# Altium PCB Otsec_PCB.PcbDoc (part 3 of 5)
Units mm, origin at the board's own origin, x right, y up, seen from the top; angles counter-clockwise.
Board outline 170 x 120 mm, 3 copper layers (Top Layer, Internal Plane 1, Bottom Layer), stack 1.608 mm thick; 1624 components, 0 nets, 5478 pads, 0 vias.
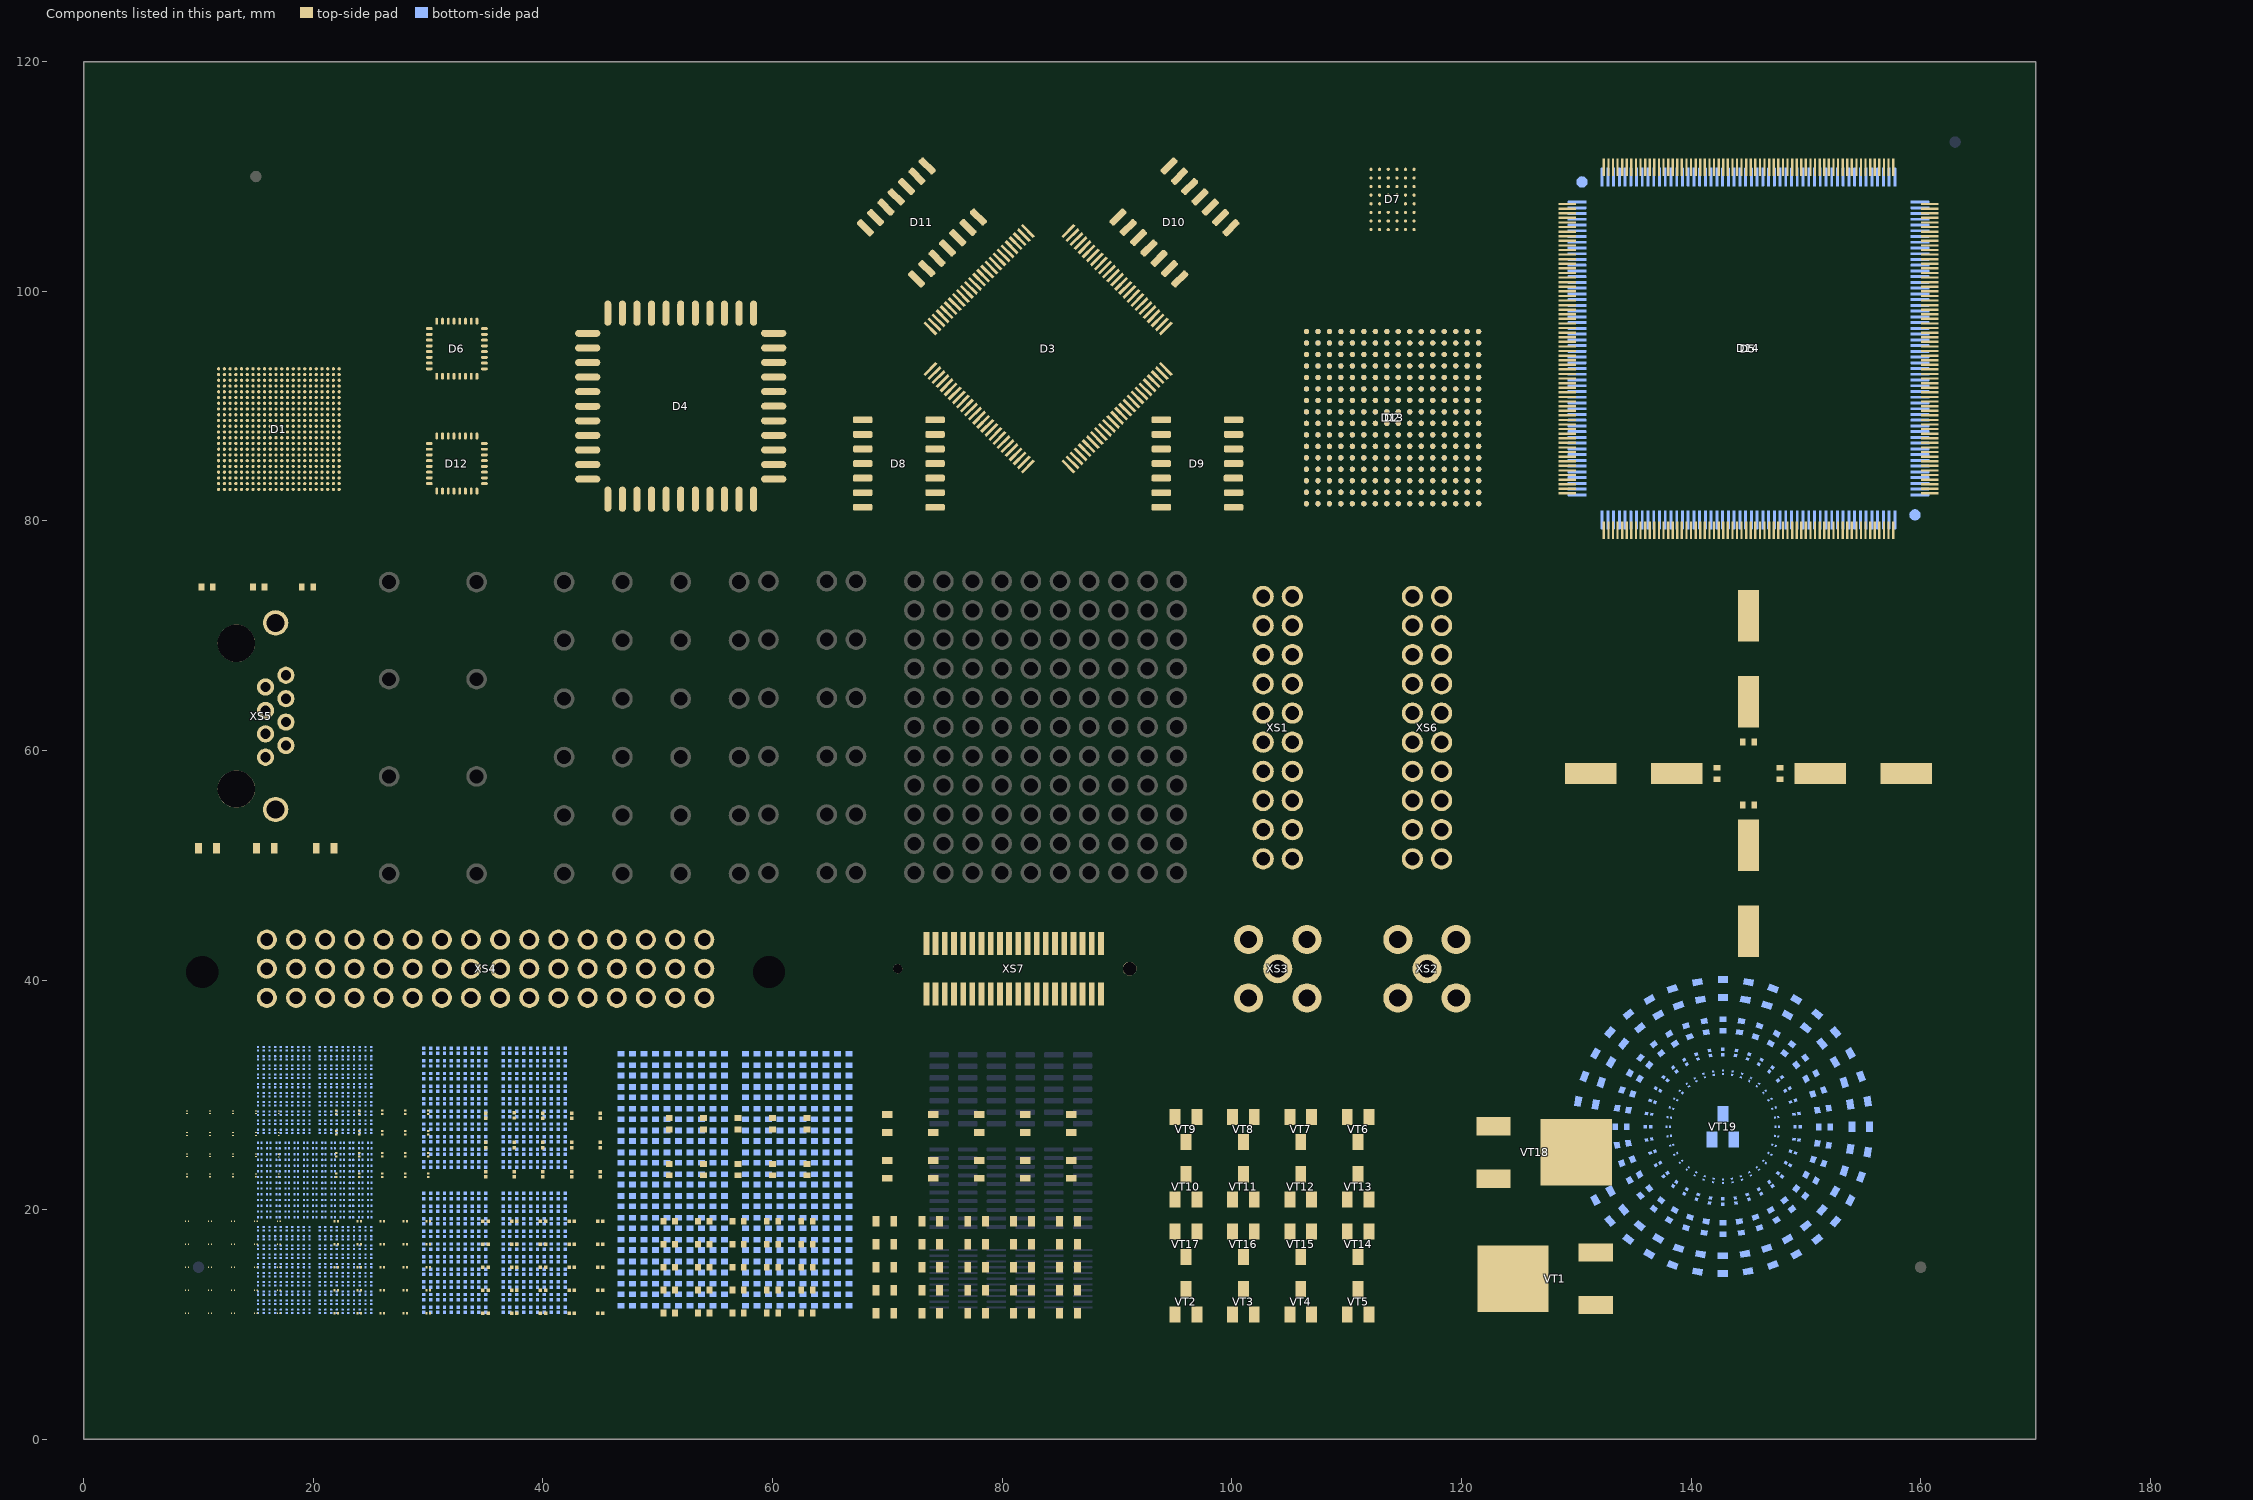
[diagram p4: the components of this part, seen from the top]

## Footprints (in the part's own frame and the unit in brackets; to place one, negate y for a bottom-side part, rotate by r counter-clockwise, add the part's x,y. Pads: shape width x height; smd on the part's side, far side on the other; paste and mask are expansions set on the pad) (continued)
QFN32 [mm]
  rrect100% 0.25x0.6 smd: 1(-1.75,-2.4) 2(-1.25,-2.4) 3(-0.75,-2.4) 4(-0.25,-2.4) 5(0.25,-2.4) 6(0.75,-2.4) 7(1.25,-2.4) 8(1.75,-2.4) 17(1.75,2.4) 18(1.25,2.4) 19(0.75,2.4) 20(0.25,2.4) 21(-0.25,2.4) 22(-0.75,2.4) 23(-1.25,2.4) 24(-1.75,2.4)
  rrect100% 0.6x0.25 smd: 9(2.4,-1.75) 10(2.4,-1.25) 11(2.4,-0.75) 12(2.4,-0.25) 13(2.4,0.25) 14(2.4,0.75) 15(2.4,1.25) 16(2.4,1.75) 25(-2.4,1.75) 26(-2.4,1.25) 27(-2.4,0.75) 28(-2.4,0.25) 29(-2.4,-0.25) 30(-2.4,-0.75) 31(-2.4,-1.25) 32(-2.4,-1.75)
  Top Layer region: -2.7,-1.625 -2.7,-1.875 -2.575,-1.875 -2.575,-1.625
  Top Layer region: -2.7,-1.125 -2.7,-1.375 -2.575,-1.375 -2.575,-1.125
  Top Layer region: -2.7,-0.625 -2.7,-0.875 -2.575,-0.875 -2.575,-0.625
  Top Layer region: -2.7,-0.125 -2.7,-0.375 -2.575,-0.375 -2.575,-0.125
  Top Layer region: -2.7,0.375 -2.7,0.125 -2.575,0.125 -2.575,0.375
  Top Layer region: -2.7,0.875 -2.7,0.625 -2.575,0.625 -2.575,0.875
  Top Layer region: -2.7,1.375 -2.7,1.125 -2.575,1.125 -2.575,1.375
  Top Layer region: -2.7,1.875 -2.7,1.625 -2.575,1.625 -2.575,1.875
  Top Layer region: -1.625,2.7 -1.875,2.7 -1.875,2.575 -1.625,2.575
  Top Layer region: -1.125,2.7 -1.375,2.7 -1.375,2.575 -1.125,2.575
  Top Layer region: -0.625,2.7 -0.875,2.7 -0.875,2.575 -0.625,2.575
  Top Layer region: -0.125,2.7 -0.375,2.7 -0.375,2.575 -0.125,2.575
  Top Layer region: 0.375,2.7 0.125,2.7 0.125,2.575 0.375,2.575
  Top Layer region: 0.875,2.7 0.625,2.7 0.625,2.575 0.875,2.575
  Top Layer region: 1.375,2.7 1.125,2.7 1.125,2.575 1.375,2.575
  Top Layer region: 1.875,2.7 1.625,2.7 1.625,2.575 1.875,2.575
  Top Layer region: 2.7,1.625 2.7,1.875 2.575,1.875 2.575,1.625
  Top Layer region: 2.7,1.125 2.7,1.375 2.575,1.375 2.575,1.125
  Top Layer region: 2.7,0.625 2.7,0.875 2.575,0.875 2.575,0.625
  Top Layer region: 2.7,0.125 2.7,0.375 2.575,0.375 2.575,0.125
  Top Layer region: 2.7,-0.375 2.7,-0.125 2.575,-0.125 2.575,-0.375
  Top Layer region: 2.7,-0.875 2.7,-0.625 2.575,-0.625 2.575,-0.875
  Top Layer region: 2.7,-1.375 2.7,-1.125 2.575,-1.125 2.575,-1.375
  Top Layer region: 2.7,-1.875 2.7,-1.625 2.575,-1.625 2.575,-1.875
  Top Layer region: 1.625,-2.7 1.875,-2.7 1.875,-2.575 1.625,-2.575
  Top Layer region: 1.125,-2.7 1.375,-2.7 1.375,-2.575 1.125,-2.575
  Top Layer region: 0.625,-2.7 0.875,-2.7 0.875,-2.575 0.625,-2.575
  Top Layer region: 0.125,-2.7 0.375,-2.7 0.375,-2.575 0.125,-2.575
  Top Layer region: -0.375,-2.7 -0.125,-2.7 -0.125,-2.575 -0.375,-2.575
  Top Layer region: -0.875,-2.7 -0.625,-2.7 -0.625,-2.575 -0.875,-2.575
  Top Layer region: -1.375,-2.7 -1.125,-2.7 -1.125,-2.575 -1.375,-2.575
  Top Layer region: -1.875,-2.7 -1.625,-2.7 -1.625,-2.575 -1.875,-2.575
  Top Layer region: 0.1,0.1 1.6,0.1 1.6,1.6 0.1,1.6
  Top Layer region: 0.1,-1.6 1.6,-1.6 1.6,-0.1 0.1,-0.1
  Top Layer region: -1.6,-1.6 -0.1,-1.6 -0.1,-0.1 -1.6,-0.1
  Top Layer region: -1.6,0.1 -0.1,0.1 -0.1,1.2 -1.6,1.2
  Top Layer region: -1.025,1.25 -0.1,1.25 -0.1,1.6 -1.025,1.6
  Top Layer region: -1.4,1.6 -1.25,1.6 -1.25,1.25 -1.6,1.25 -1.6,1.4
  Top Layer region: -1.25,1.6 -1.025,1.6 -1.025,1.25 -1.25,1.25
  Top Layer region: -1.6,1.25 -0.1,1.25 -0.1,1.15 -1.6,1.15
  silkscreen extent -3.11,-2.55 2.55,3.17, body extent -2.55,-2.55 2.55,2.55, height 1.04
QFN32_2 [mm]
  rrect100% 0.25x0.6 smd: 1(-1.75,-2.4) 2(-1.25,-2.4) 3(-0.75,-2.4) 4(-0.25,-2.4) 5(0.25,-2.4) 6(0.75,-2.4) 7(1.25,-2.4) 8(1.75,-2.4) 17(1.75,2.4) 18(1.25,2.4) 19(0.75,2.4) 20(0.25,2.4) 21(-0.25,2.4) 22(-0.75,2.4) 23(-1.25,2.4) 24(-1.75,2.4)
  rrect100% 0.6x0.25 smd: 9(2.4,-1.75) 10(2.4,-1.25) 11(2.4,-0.75) 12(2.4,-0.25) 13(2.4,0.25) 14(2.4,0.75) 15(2.4,1.25) 16(2.4,1.75) 25(-2.4,1.75) 26(-2.4,1.25) 27(-2.4,0.75) 28(-2.4,0.25) 29(-2.4,-0.25) 30(-2.4,-0.75) 31(-2.4,-1.25) 32(-2.4,-1.75)
  Top Layer region: -2.7,-1.625 -2.7,-1.875 -2.575,-1.875 -2.575,-1.625
  Top Layer region: -2.7,-1.125 -2.7,-1.375 -2.575,-1.375 -2.575,-1.125
  Top Layer region: -2.7,-0.625 -2.7,-0.875 -2.575,-0.875 -2.575,-0.625
  Top Layer region: -2.7,-0.125 -2.7,-0.375 -2.575,-0.375 -2.575,-0.125
  Top Layer region: -2.7,0.375 -2.7,0.125 -2.575,0.125 -2.575,0.375
  Top Layer region: -2.7,0.875 -2.7,0.625 -2.575,0.625 -2.575,0.875
  Top Layer region: -2.7,1.375 -2.7,1.125 -2.575,1.125 -2.575,1.375
  Top Layer region: -2.7,1.875 -2.7,1.625 -2.575,1.625 -2.575,1.875
  Top Layer region: -1.625,2.7 -1.875,2.7 -1.875,2.575 -1.625,2.575
  Top Layer region: -1.125,2.7 -1.375,2.7 -1.375,2.575 -1.125,2.575
  Top Layer region: -0.625,2.7 -0.875,2.7 -0.875,2.575 -0.625,2.575
  Top Layer region: -0.125,2.7 -0.375,2.7 -0.375,2.575 -0.125,2.575
  Top Layer region: 0.375,2.7 0.125,2.7 0.125,2.575 0.375,2.575
  Top Layer region: 0.875,2.7 0.625,2.7 0.625,2.575 0.875,2.575
  Top Layer region: 1.375,2.7 1.125,2.7 1.125,2.575 1.375,2.575
  Top Layer region: 1.875,2.7 1.625,2.7 1.625,2.575 1.875,2.575
  Top Layer region: 2.7,1.625 2.7,1.875 2.575,1.875 2.575,1.625
  Top Layer region: 2.7,1.125 2.7,1.375 2.575,1.375 2.575,1.125
  Top Layer region: 2.7,0.625 2.7,0.875 2.575,0.875 2.575,0.625
  Top Layer region: 2.7,0.125 2.7,0.375 2.575,0.375 2.575,0.125
  Top Layer region: 2.7,-0.375 2.7,-0.125 2.575,-0.125 2.575,-0.375
  Top Layer region: 2.7,-0.875 2.7,-0.625 2.575,-0.625 2.575,-0.875
  Top Layer region: 2.7,-1.375 2.7,-1.125 2.575,-1.125 2.575,-1.375
  Top Layer region: 2.7,-1.875 2.7,-1.625 2.575,-1.625 2.575,-1.875
  Top Layer region: 1.625,-2.7 1.875,-2.7 1.875,-2.575 1.625,-2.575
  Top Layer region: 1.125,-2.7 1.375,-2.7 1.375,-2.575 1.125,-2.575
  Top Layer region: 0.625,-2.7 0.875,-2.7 0.875,-2.575 0.625,-2.575
  Top Layer region: 0.125,-2.7 0.375,-2.7 0.375,-2.575 0.125,-2.575
  Top Layer region: -0.375,-2.7 -0.125,-2.7 -0.125,-2.575 -0.375,-2.575
  Top Layer region: -0.875,-2.7 -0.625,-2.7 -0.625,-2.575 -0.875,-2.575
  Top Layer region: -1.375,-2.7 -1.125,-2.7 -1.125,-2.575 -1.375,-2.575
  Top Layer region: -1.875,-2.7 -1.625,-2.7 -1.625,-2.575 -1.875,-2.575
  Top Layer region: -0.05,0.025 1.6,0.025 1.6,1.6 -0.05,1.6
  Top Layer region: -0.075,-1.6 1.6,-1.6 1.6,0.05 -0.075,0.05
  Top Layer region: -1.6,-1.6 -0.025,-1.6 -0.025,0.075 -1.6,0.075
  Top Layer region: -1.6,0.025 -0.025,0.025 -0.025,1.15 -1.6,1.15
  Top Layer region: -1.025,1.25 -0.025,1.25 -0.025,1.6 -1.025,1.6
  Top Layer region: -1.4,1.6 -1.25,1.6 -1.25,1.25 -1.6,1.25 -1.6,1.4
  Top Layer region: -1.25,1.6 -1.025,1.6 -1.025,1.25 -1.25,1.25
  Top Layer region: -1.6,1.25 -0.025,1.25 -0.025,1.15 -1.6,1.15
  silkscreen extent -3.11,-2.55 2.55,3.17, body extent -2.55,-2.55 2.55,2.55, height 1.04
QFP100_0.5 [mm]
  rect 1.5x0.254 smd: 1(-8.5,6) 2(-8.5,5.5) 3(-8.5,5) 4(-8.5,4.5) 5(-8.5,4) 6(-8.5,3.5) 7(-8.5,3) 8(-8.5,2.5) 9(-8.5,2) 10(-8.5,1.5) 11(-8.5,1) 12(-8.5,0.5) 13(-8.5,0) 14(-8.5,-0.5) 15(-8.5,-1) 16(-8.5,-1.5) 17(-8.5,-2) 18(-8.5,-2.5) 19(-8.5,-3) 20(-8.5,-3.5) 21(-8.5,-4) 22(-8.5,-4.5) 23(-8.5,-5) 24(-8.5,-5.5) 25(-8.5,-6) 51(8.5,-6) 52(8.5,-5.5) 53(8.5,-5) 54(8.5,-4.5) 55(8.5,-4) 56(8.5,-3.5) 57(8.5,-3) 58(8.5,-2.5) 59(8.5,-2) 60(8.5,-1.5) 61(8.5,-1) 62(8.5,-0.5) 63(8.5,0) 64(8.5,0.5) 65(8.5,1) 66(8.5,1.5) 67(8.5,2) 68(8.5,2.5) 69(8.5,3) 70(8.5,3.5) 71(8.5,4) 72(8.5,4.5) 73(8.5,5) 74(8.5,5.5) 75(8.5,6)
  rect 0.254x1.5 smd: 26(-6,-8.5) 27(-5.5,-8.5) 28(-5,-8.5) 29(-4.5,-8.5) 30(-4,-8.5) 31(-3.5,-8.5) 32(-3,-8.5) 33(-2.5,-8.5) 34(-2,-8.5) 35(-1.5,-8.5) 36(-1,-8.5) 37(-0.5,-8.5) 38(0,-8.5) 39(0.5,-8.5) 40(1,-8.5) 41(1.5,-8.5) 42(2,-8.5) 43(2.5,-8.5) 44(3,-8.5) 45(3.5,-8.5) 46(4,-8.5) 47(4.5,-8.5) 48(5,-8.5) 49(5.5,-8.5) 50(6,-8.5) 76(6,8.5) 77(5.5,8.5) 78(5,8.5) 79(4.5,8.5) 80(4,8.5) 81(3.5,8.5) 82(3,8.5) 83(2.5,8.5) 84(2,8.5) 85(1.5,8.5) 86(1,8.5) 87(0.5,8.5) 88(0,8.5) 89(-0.5,8.5) 90(-1,8.5) 91(-1.5,8.5) 92(-2,8.5) 93(-2.5,8.5) 94(-3,8.5) 95(-3.5,8.5) 96(-4,8.5) 97(-4.5,8.5) 98(-5,8.5) 99(-5.5,8.5) 100(-6,8.5)
  silkscreen extent -7.9,-7.21 7.21,7.9, body extent -8,-8 8,8, height 1.6
QFP208 [mm]
  rrect40% 0.254x1.65 smd: 1(-12.75,-14.925) 2(-12.25,-14.925) 3(-11.75,-14.925) 4(-11.25,-14.925) 5(-10.75,-14.925) 6(-10.25,-14.925) 7(-9.75,-14.925) 8(-9.25,-14.925) 9(-8.75,-14.925) 10(-8.25,-14.925) 11(-7.75,-14.925) 12(-7.25,-14.925) 13(-6.75,-14.925) 14(-6.25,-14.925) 15(-5.75,-14.925) 16(-5.25,-14.925) 17(-4.75,-14.925) 18(-4.25,-14.925) 19(-3.75,-14.925) 20(-3.25,-14.925) 21(-2.75,-14.925) 22(-2.25,-14.925) 23(-1.75,-14.925) 24(-1.25,-14.925) 25(-0.75,-14.925) 26(-0.25,-14.925) 27(0.25,-14.925) 28(0.75,-14.925) 29(1.25,-14.925) 30(1.75,-14.925) 31(2.25,-14.925) 32(2.75,-14.925) 33(3.25,-14.925) 34(3.75,-14.925) 35(4.25,-14.925) 36(4.75,-14.925) 37(5.25,-14.925) 38(5.75,-14.925) 39(6.25,-14.925) 40(6.75,-14.925) 41(7.25,-14.925) 42(7.75,-14.925) 43(8.25,-14.925) 44(8.75,-14.925) 45(9.25,-14.925) 46(9.75,-14.925) 47(10.25,-14.925) 48(10.75,-14.925) 49(11.25,-14.925) 50(11.75,-14.925) 51(12.25,-14.925) 52(12.75,-14.925) 105(12.75,14.925) 106(12.25,14.925) 107(11.75,14.925) 108(11.25,14.925) 109(10.75,14.925) 110(10.25,14.925) 111(9.75,14.925) 112(9.25,14.925) 113(8.75,14.925) 114(8.25,14.925) 115(7.75,14.925) 116(7.25,14.925) 117(6.75,14.925) 118(6.25,14.925) 119(5.75,14.925) 120(5.25,14.925) 121(4.75,14.925) 122(4.25,14.925) 123(3.75,14.925) 124(3.25,14.925) 125(2.75,14.925) 126(2.25,14.925) 127(1.75,14.925) 128(1.25,14.925) 129(0.75,14.925) 130(0.25,14.925) 131(-0.25,14.925) 132(-0.75,14.925) 133(-1.25,14.925) 134(-1.75,14.925) 135(-2.25,14.925) 136(-2.75,14.925) 137(-3.25,14.925) 138(-3.75,14.925) 139(-4.25,14.925) 140(-4.75,14.925) 141(-5.25,14.925) 142(-5.75,14.925) 143(-6.25,14.925) 144(-6.75,14.925) 145(-7.25,14.925) 146(-7.75,14.925) 147(-8.25,14.925) 148(-8.75,14.925) 149(-9.25,14.925) 150(-9.75,14.925) 151(-10.25,14.925) 152(-10.75,14.925) 153(-11.25,14.925) 154(-11.75,14.925) 155(-12.25,14.925) 156(-12.75,14.925)
  rrect40% 1.65x0.254 smd: 53(14.925,-12.75) 54(14.925,-12.25) 55(14.925,-11.75) 56(14.925,-11.25) 57(14.925,-10.75) 58(14.925,-10.25) 59(14.925,-9.75) 60(14.925,-9.25) 61(14.925,-8.75) 62(14.925,-8.25) 63(14.925,-7.75) 64(14.925,-7.25) 65(14.925,-6.75) 66(14.925,-6.25) 67(14.925,-5.75) 68(14.925,-5.25) 69(14.925,-4.75) 70(14.925,-4.25) 71(14.925,-3.75) 72(14.925,-3.25) 73(14.925,-2.75) 74(14.925,-2.25) 75(14.925,-1.75) 76(14.925,-1.25) 77(14.925,-0.75) 78(14.925,-0.25) 79(14.925,0.25) 80(14.925,0.75) 81(14.925,1.25) 82(14.925,1.75) 83(14.925,2.25) 84(14.925,2.75) 85(14.925,3.25) 86(14.925,3.75) 87(14.925,4.25) 88(14.925,4.75) 89(14.925,5.25) 90(14.925,5.75) 91(14.925,6.25) 92(14.925,6.75) 93(14.925,7.25) 94(14.925,7.75) 95(14.925,8.25) 96(14.925,8.75) 97(14.925,9.25) 98(14.925,9.75) 99(14.925,10.25) 100(14.925,10.75) 101(14.925,11.25) 102(14.925,11.75) 103(14.925,12.25) 104(14.925,12.75) 157(-14.925,12.75) 158(-14.925,12.25) 159(-14.925,11.75) 160(-14.925,11.25) 161(-14.925,10.75) 162(-14.925,10.25) 163(-14.925,9.75) 164(-14.925,9.25) 165(-14.925,8.75) 166(-14.925,8.25) 167(-14.925,7.75) 168(-14.925,7.25) 169(-14.925,6.75) 170(-14.925,6.25) 171(-14.925,5.75) 172(-14.925,5.25) 173(-14.925,4.75) 174(-14.925,4.25) 175(-14.925,3.75) 176(-14.925,3.25) 177(-14.925,2.75) 178(-14.925,2.25) 179(-14.925,1.75) 180(-14.925,1.25) 181(-14.925,0.75) 182(-14.925,0.25) 183(-14.925,-0.25) 184(-14.925,-0.75) 185(-14.925,-1.25) 186(-14.925,-1.75) 187(-14.925,-2.25) 188(-14.925,-2.75) 189(-14.925,-3.25) 190(-14.925,-3.75) 191(-14.925,-4.25) 192(-14.925,-4.75) 193(-14.925,-5.25) 194(-14.925,-5.75) 195(-14.925,-6.25) 196(-14.925,-6.75) 197(-14.925,-7.25) 198(-14.925,-7.75) 199(-14.925,-8.25) 200(-14.925,-8.75) 201(-14.925,-9.25) 202(-14.925,-9.75) 203(-14.925,-10.25) 204(-14.925,-10.75) 205(-14.925,-11.25) 206(-14.925,-11.75) 207(-14.925,-12.25) 208(-14.925,-12.75)
  round 1 smd mask+0.5: ""(-14.5,-14.5) ""(14.5,14.5)
  silkscreen extent -15.83,-13.52 13.52,15.8, body extent -15.3,-15.3 15.3,15.3, height 4.15
QFP256 [mm]
  rect 1.52x0.2 smd: 1(-15.8,12.6) 2(-15.8,12.2) 3(-15.8,11.8) 4(-15.8,11.4) 5(-15.8,11) 6(-15.8,10.6) 7(-15.8,10.2) 8(-15.8,9.8) 9(-15.8,9.4) 10(-15.8,9) 11(-15.8,8.6) 12(-15.8,8.2) 13(-15.8,7.8) 14(-15.8,7.4) 15(-15.8,7) 16(-15.8,6.6) 17(-15.8,6.2) 18(-15.8,5.8) 19(-15.8,5.4) 20(-15.8,5) 21(-15.8,4.6) 22(-15.8,4.2) 23(-15.8,3.8) 24(-15.8,3.4) 25(-15.8,3) 26(-15.8,2.6) 27(-15.8,2.2) 28(-15.8,1.8) 29(-15.8,1.4) 30(-15.8,1) 31(-15.8,0.6) 32(-15.8,0.2) 33(-15.8,-0.2) 34(-15.8,-0.6) 35(-15.8,-1) 36(-15.8,-1.4) 37(-15.8,-1.8) 38(-15.8,-2.2) 39(-15.8,-2.6) 40(-15.8,-3) 41(-15.8,-3.4) 42(-15.8,-3.8) 43(-15.8,-4.2) 44(-15.8,-4.6) 45(-15.8,-5) 46(-15.8,-5.4) 47(-15.8,-5.8) 48(-15.8,-6.2) 49(-15.8,-6.6) 50(-15.8,-7) 51(-15.8,-7.4) 52(-15.8,-7.8) 53(-15.8,-8.2) 54(-15.8,-8.6) 55(-15.8,-9) 56(-15.8,-9.4) 57(-15.8,-9.8) 58(-15.8,-10.2) 59(-15.8,-10.6) 60(-15.8,-11) 61(-15.8,-11.4) 62(-15.8,-11.8) 63(-15.8,-12.2) 64(-15.8,-12.6) 129(15.8,-12.6) 130(15.8,-12.2) 131(15.8,-11.8) 132(15.8,-11.4) 133(15.8,-11) 134(15.8,-10.6) 135(15.8,-10.2) 136(15.8,-9.8) 137(15.8,-9.4) 138(15.8,-9) 139(15.8,-8.6) 140(15.8,-8.2) 141(15.8,-7.8) 142(15.8,-7.4) 143(15.8,-7) 144(15.8,-6.6) 145(15.8,-6.2) 146(15.8,-5.8) 147(15.8,-5.4) 148(15.8,-5) 149(15.8,-4.6) 150(15.8,-4.2) 151(15.8,-3.8) 152(15.8,-3.4) 153(15.8,-3) 154(15.8,-2.6) 155(15.8,-2.2) 156(15.8,-1.8) 157(15.8,-1.4) 158(15.8,-1) 159(15.8,-0.6) 160(15.8,-0.2) 161(15.8,0.2) 162(15.8,0.6) 163(15.8,1) 164(15.8,1.4) 165(15.8,1.8) 166(15.8,2.2) 167(15.8,2.6) 168(15.8,3) 169(15.8,3.4) 170(15.8,3.8) 171(15.8,4.2) 172(15.8,4.6) 173(15.8,5) 174(15.8,5.4) 175(15.8,5.8) 176(15.8,6.2) 177(15.8,6.6) 178(15.8,7) 179(15.8,7.4) 180(15.8,7.8) 181(15.8,8.2) 182(15.8,8.6) 183(15.8,9) 184(15.8,9.4) 185(15.8,9.8) 186(15.8,10.2) 187(15.8,10.6) 188(15.8,11) 189(15.8,11.4) 190(15.8,11.8) 191(15.8,12.2) 192(15.8,12.6)
  rect 0.2x1.52 smd: 65(-12.6,-15.8) 66(-12.2,-15.8) 67(-11.8,-15.8) 68(-11.4,-15.8) 69(-11,-15.8) 70(-10.6,-15.8) 71(-10.2,-15.8) 72(-9.8,-15.8) 73(-9.4,-15.8) 74(-9,-15.8) 75(-8.6,-15.8) 76(-8.2,-15.8) 77(-7.8,-15.8) 78(-7.4,-15.8) 79(-7,-15.8) 80(-6.6,-15.8) 81(-6.2,-15.8) 82(-5.8,-15.8) 83(-5.4,-15.8) 84(-5,-15.8) 85(-4.6,-15.8) 86(-4.2,-15.8) 87(-3.8,-15.8) 88(-3.4,-15.8) 89(-3,-15.8) 90(-2.6,-15.8) 91(-2.2,-15.8) 92(-1.8,-15.8) 93(-1.4,-15.8) 94(-1,-15.8) 95(-0.6,-15.8) 96(-0.2,-15.8) 97(0.2,-15.8) 98(0.6,-15.8) 99(1,-15.8) 100(1.4,-15.8) 101(1.8,-15.8) 102(2.2,-15.8) 103(2.6,-15.8) 104(3,-15.8) 105(3.4,-15.8) 106(3.8,-15.8) 107(4.2,-15.8) 108(4.6,-15.8) 109(5,-15.8) 110(5.4,-15.8) 111(5.8,-15.8) 112(6.2,-15.8) 113(6.6,-15.8) 114(7,-15.8) 115(7.4,-15.8) 116(7.8,-15.8) 117(8.2,-15.8) 118(8.6,-15.8) 119(9,-15.8) 120(9.4,-15.8) 121(9.8,-15.8) 122(10.2,-15.8) 123(10.6,-15.8) 124(11,-15.8) 125(11.4,-15.8) 126(11.8,-15.8) 127(12.2,-15.8) 128(12.6,-15.8) 193(12.6,15.8) 194(12.2,15.8) 195(11.8,15.8) 196(11.4,15.8) 197(11,15.8) 198(10.6,15.8) 199(10.2,15.8) 200(9.8,15.8) 201(9.4,15.8) 202(9,15.8) 203(8.6,15.8) 204(8.2,15.8) 205(7.8,15.8) 206(7.4,15.8) 207(7,15.8) 208(6.6,15.8) 209(6.2,15.8) 210(5.8,15.8) 211(5.4,15.8) 212(5,15.8) 213(4.6,15.8) 214(4.2,15.8) 215(3.8,15.8) 216(3.4,15.8) 217(3,15.8) 218(2.6,15.8) 219(2.2,15.8) 220(1.8,15.8) 221(1.4,15.8) 222(1,15.8) 223(0.6,15.8) 224(0.2,15.8) 225(-0.2,15.8) 226(-0.6,15.8) 227(-1,15.8) 228(-1.4,15.8) 229(-1.8,15.8) 230(-2.2,15.8) 231(-2.6,15.8) 232(-3,15.8) 233(-3.4,15.8) 234(-3.8,15.8) 235(-4.2,15.8) 236(-4.6,15.8) 237(-5,15.8) 238(-5.4,15.8) 239(-5.8,15.8) 240(-6.2,15.8) 241(-6.6,15.8) 242(-7,15.8) 243(-7.4,15.8) 244(-7.8,15.8) 245(-8.2,15.8) 246(-8.6,15.8) 247(-9,15.8) 248(-9.4,15.8) 249(-9.8,15.8) 250(-10.2,15.8) 251(-10.6,15.8) 252(-11,15.8) 253(-11.4,15.8) 254(-11.8,15.8) 255(-12.2,15.8) 256(-12.6,15.8)
  Top Layer circle w0.2: c15.5,15.5 r0.4
  Top Layer circle w0.2: c-15.5,-15.5 r0.4
  Top Layer region: 15.2,15.2 15.8,15.2 15.8,15.8 15.2,15.8
  Top Layer region: -15.8,-15.8 -15.2,-15.8 -15.2,-15.2 -15.8,-15.2
  silkscreen extent -15.4,-14.5 14.5,15.4, body extent -15.88,-15.88 15.88,15.88, height 3.66
R0201 [mm]
  rect 0.3x0.3 smd: 1(-0.225,0) 2(0.225,0)
  silkscreen extent -0.63,-0.4 0.63,0.4, body extent -0.3,-0.15 0.3,0.15, height 0.15
R0201_nosilk [mm]
  rect 0.3x0.3 smd: 1(-0.225,0) 2(0.225,0)
  body extent -0.3,-0.15 0.3,0.15, height 0.15
R0402 [mm]
  rect 0.5x0.6 smd: 1(-0.5,0) 2(0.5,0)
  silkscreen extent -0.97,-0.53 0.97,0.53, body extent -0.52,-0.3 0.52,0.3, height 0.34
R0402_NOSILK [mm]
  rect 0.5x0.6 smd: 1(-0.5,0) 2(0.5,0)
  body extent -0.52,-0.3 0.52,0.3, height 0.34
R0603 [mm]
  rect 0.6x0.9 smd: 1(-0.75,0) 2(0.8,0)
  silkscreen extent -1.28,-0.67 1.33,0.67, body extent -0.8,-0.4 0.8,0.4, height 0.45
R0603_NOSILK [mm]
  rect 0.6x0.9 smd: 1(-0.75,0) 2(0.8,0)
  body extent -0.8,-0.4 0.8,0.4, height 0.45
R01005 [mm]
  rrect25% 0.18x0.2 smd: 1(-0.15,0) 2(0.15,0)
  body extent -0.2,-0.1 0.2,0.1, height 0.12
R03015 [mm]
  rrect50% 0.1x0.15 smd: 1(-0.12,0) 2(0.12,0)
  body extent -0.15,-0.07 0.15,0.08, height 0.1
RJ-45 [mm]
  round 1.5 hole 0.89: 1(3.58,7.83) 2(2.56,9.61) 3(1.54,7.83) 4(0.52,9.61) 5(-0.5,7.83) 6(-1.52,9.61) 7(-2.54,7.83) 8(-3.56,9.61)
  round 2.2 hole 1.57 unplated: ""(-8.13,8.72) ""(8.13,8.72)
  round 3.25 hole 3.25 unplated: ""(-6.35,5.29) ""(6.35,5.29)
  silkscreen extent -9.5,-1.25 9.5,16, body extent -9.32,0 9.32,15.75, height 14.6
SO14 [mm]
  rrect50% 1.7x0.6 smd: 1(-3.15,-3.81) 2(-3.15,-2.54) 3(-3.15,-1.27) 4(-3.15,0) 5(-3.14,1.27) 6(-3.15,2.54) 7(-3.15,3.81) 8(3.15,3.81) 9(3.15,2.54) 10(3.15,1.27) 11(3.15,0) 12(3.15,-1.27) 13(3.15,-2.54) 14(3.15,-3.81)
  silkscreen extent -1.9,-4.38 1.9,4.38, body extent -3,-4.38 3,4.37, height 1.75
SOT23 [mm]
  rect 0.95x1.4 smd: 1(0,1.1) 2(0.95,-1.1) 3(-0.95,-1.1)
  silkscreen extent -1.7,-0.7 1.7,0.7, body extent -1.5,-1.25 1.5,1.25, height 1.05
uBGA46 [mm]
  round 0.28 smd: 1(-1.875,2.625) 2(-1.125,2.625) 3(-0.375,2.625) 4(0.375,2.625) 5(1.125,2.625) 6(1.875,2.625) 7(-1.875,1.875) 8(-1.125,1.875) 9(-0.375,1.875) 10(0.375,1.875) 11(1.125,1.875) 12(1.875,1.875) 13(-1.875,1.125) 14(-1.125,1.125) 15(-0.375,1.125) 16(0.375,1.125) 17(1.125,1.125) 18(1.875,1.125) 19(-1.875,0.375) 20(-1.125,0.375) 21(-0.375,0.375) 22(0.375,0.375) 23(1.125,0.375) 24(1.875,0.375) 25(-1.875,-0.375) 26(-1.125,-0.375) 27(1.125,-0.375) 28(1.875,-0.375) 29(-1.875,-1.125) 30(-1.125,-1.125) 31(-0.375,-1.125) 32(0.375,-1.125) 33(1.125,-1.125) 34(1.875,-1.125) 35(-1.875,-1.875) 36(-1.125,-1.875) 37(-0.375,-1.875) 38(0.375,-1.875) 39(1.125,-1.875) 40(1.875,-1.875) 41(-1.875,-2.625) 42(-1.125,-2.625) 43(-0.375,-2.625) 44(0.375,-2.625) 45(1.125,-2.625) 46(1.875,-2.625)
  silkscreen extent -3.74,-3.5 3,4.24, body extent -3,-3.5 3,3.5, height 1.12
UCH_Socket [mm]
  round 2.54 hole 1.5: 1(0,0) 2(-2.54,2.54) 3(2.54,2.54) 4(-2.54,-2.54) 5(2.54,-2.54)
  silkscreen extent -4.25,-4.25 4.25,4.25, body extent -3.13,-3.13 3.13,3.13, height 9.55

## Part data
C1 C2 C3 C4: library part Capacitor
D1: Case=BGA-484, Manufacture=TopLine
D2 D13: Case=BGA-256, Manufacture=TopLine
D3: Case=QFP-100, Manufacture=TopLine
D4: Manufacture=TopLine
D5: library part QFP256T15.7, Case=QFP256, Manufacture=TopLine
D6 D12: Case=MELF-32, Manufacture=TopLine
D7: Case=uBGA-46, Manufacture=TopLine
D8 D9 D10 D11: Case=SOIC-14, Manufacture=TopLine
D14: Case=QFP-208, Manufacture=TopLine
R1 R2 R3 R4 R5 R6 R7 R8 R9 R10 R11 R12 R13 R14 R15 R16 R17 R18 R19 R20 R21 R22 R23 R24 R25 R26 R27 R28 R29 R30 R31 R32 R33 R34 R35 R36 R37 R38 R39 R40 R41 R42 R43 R44 R45 R46 R47 R48 R49 R50 R51 R52 R53 R54 R55 R56 R57 R58 R59 R60 R61 R62 R63 R64 R65 R66 R67 R68 R69 R70 R71 R72 R73 R74 R75 R76 R77 R78 R79 R80 R81 R82 R83 R84 R85 R86 R87 R88 R89 R90 R91 R92 R93 R94 R95 R96 R97 R98 R99 R100 R101 R102 R103 R104 R105 R106 R107 R108 R109 R110 R111 R112 R113 R114 R115 R116 R117 R118 R119 R120 R121 R122 R123 R124 R125 R126 R127 R128 R129 R130 R131 R132 R133 R134 R135 R136 R137 R138 R139 R140 R141 R142 R143 R144 R145 R146 R147 R148 R149 R150 R151 R152 R153 R154 R155 R156 R157 R158 R159 R160 R161 R162 R163 R164 R165 R166 R167 R168 R169 R170 R171 R172 R173 R174 R175 R176 R177 R178 R179 R180 R181 R182 R183 R184 R185 R186 R187 R188 R189 R190 R191 R192 R193 R194 R195 R196 R197 R198 R199 R200 R201 R202 R203 R204 R205 R206 R207 R208 R209 R210 R211 R211_1 R211_1_1 R211_2 R211_3 R211_3_1 R211_3_1_1 R211_3_2 R212 R212_1 R212_1_1 R212_2 R212_3 R212_3_1 R212_3_1_1 R212_3_2 R213 R213_1 R213_1_1 R213_2 R213_3 R213_3_1 R213_3_1_1 R213_3_2 R214 R214_1 R214_1_1 R214_2 R214_3 R214_3_1 R215 R215_1 R215_1_1 R215_2 R215_3 R215_3_1 R216 R216_1 R216_1_1 R216_2 R216_3 R217 R217_1 R217_1_1 R217_2 R217_3 R218 R218_1 R218_1_1 R218_2 R218_3 R219 R219_1 R219_1_1 R219_2 R219_3 R220 R220_1 R220_1_1 R220_2 R220_3 R220_3_1 R220_3_1_1 R220_3_2 R221 R221_1 R221_1_1 R221_2 R221_3 R221_3_1 R222 R222_1 R222_1_1 R222_2 R222_3 R223 R223_1 R223_1_1 R223_2 R223_3 R224 R224_1 R224_1_1 R224_2 R224_3 R224_3_1 R225 R225_1 R225_1_1 R225_2 R225_3 R225_3_1 R226 R226_1 R226_1_1 R226_2 R226_3 R226_3_1 R227 R227_1 R227_1_1 R227_2 R227_3 R227_3_1 R228 R228_1 R228_1_1 R228_2 R228_3 R228_3_1 R229 R229_1 R229_1_1 R229_2 R229_3 R229_3_1 R230 R230_1 R230_1_1 R230_2 R230_3 R230_3_1 R231 R231_1 R231_1_1 R231_2 R231_3 R232 R232_1 R232_1_1 R232_2 R232_3 R233 R233_1 R233_1_1 R233_2 R233_3 R234 R234_1 R234_1_1 R234_2 R234_3 R235 R235_1 R235_1_1 R235_2 R235_3 R236 R236_1 R236_1_1 R236_2 R236_3 R236_3_1 R237 R237_1 R237_1_1 R237_2 R237_3 R237_3_1 R238 R238_1 R238_1_1 R238_2 R238_3 R238_3_1 R239 R239_1 R239_1_1 R239_2 R239_3 R240 R240_1 R240_1_1 R240_2 R240_3 R240_3_1 R241 R241_1 R241_1_1 R241_2 R241_3 R241_3_1 R241_3_1_1 R241_3_2 R242 R242_1 R242_1_1 R242_2 R242_3 R242_3_1 R242_3_1_1 R242_3_2 R243 R243_1 R243_1_1 R243_2 R243_3 R243_3_1 R244 R244_1 R244_1_1 R244_2 R244_3 R245 R245_1 R245_1_1 R245_2 R245_3 R246 R246_1 R246_1_1 R246_2 R246_3 R247 R247_1 R247_1_1 R247_2 R247_3 R247_3_1 R248 R248_1 R248_1_1 R248_2 R248_3 R248_3_1 R249 R249_1 R249_1_1 R249_2 R249_3 R249_3_1 R250 R250_1 R250_1_1 R250_2 R250_3 R250_3_1 R251 R251_1 R251_1_1 R251_2 R251_3 R252 R252_1 R252_1_1 R252_2 R252_3 R252_3_1 R253 R253_1 R253_1_1 R253_2 R253_3 R253_3_1 R254 R254_1 R254_1_1 R254_2 R254_3 R255 R255_1 R255_1_1 R255_2 R255_3 R256 R256_1 R256_1_1 R256_2 R256_3 R256_3_1 R257 R257_1 R257_1_1 R257_2 R257_3 R257_3_1 R258 R258_1 R258_1_1 R258_2 R258_3 R259 R259_1 R259_1_1 R259_2 R259_3 R260 R260_1 R260_1_1 R260_2 R260_3 R261 R261_1 R261_1_1 R261_2 R261_3 R262 R262_1 R262_1_1 R262_2 R262_3 R263 R263_1 R263_1_1 R263_2 R263_3 R263_3_1 R264 R264_1 R264_1_1 R264_2 R264_3 R264_3_1 R264_3_1_1 R264_3_2 R265 R265_1 R265_1_1 R265_2 R265_3 R265_3_1 R265_3_1_1 R265_3_2 R266 R266_1 R266_1_1 R266_2 R266_3 R266_3_1 R267 R267_1 R267_1_1 R267_2 R267_3 R267_3_1 R268 R268_1 R268_1_1 R268_2 R268_3 R269 R269_1 R269_1_1 R269_2 R269_3 R270 R270_1 R270_1_1 R270_2 R270_3 R271 R271_1 R271_1_1 R271_2 R271_3 R271_3_1 R271_3_1_1 R271_3_2 R272 R272_1 R272_1_1 R272_2 R272_3 R272_3_1 R273 R273_1 R273_1_1 R273_2 R273_3 R273_3_1 R274 R274_1 R274_1_1 R274_2 R274_3 R274_3_1 R275 R275_1 R275_1_1 R275_2 R275_3 R275_3_1 R276 R276_1 R276_1_1 R276_2 R276_3 R276_3_1 R276_3_1_1 R276_3_2 R277 R277_1 R277_1_1 R277_2 R277_3 R277_3_1 R278 R278_1 R278_1_1 R278_2 R278_3 R278_3_1 R279 R279_1 R279_1_1 R279_2 R279_3 R279_3_1 R280 R280_1 R280_1_1 R280_2 R280_3 R280_3_1 R280_3_1_1 R280_3_2 R281 R281_1 R281_1_1 R281_2 R281_3 R282 R282_1 R282_1_1 R282_2 R282_3 R283 R283_1 R283_1_1 R283_2 R283_3 R284 R284_1 R284_1_1 R284_2 R284_3 R285 R285_1 R285_1_1 R285_2 R285_3 R285_3_1 R285_3_1_1 R285_3_2 R286 R286_1 R286_1_1 R286_2 R286_3 R287 R287_1 R287_1_1 R287_2 R287_3 R288 R288_1 R288_1_1 R288_2 R288_3 R289 R289_1 R289_1_1 R289_2 R289_3 R289_3_1 R290 R290_1 R290_1_1 R290_2 R290_3 R291 R291_1 R291_1_1 R291_2 R291_3 R291_3_1 R292 R292_1 R292_1_1 R292_2 R292_3 R292_3_1 R293 R293_1 R293_1_1 R293_2 R293_3 R293_3_1 R294 R294_1 R294_1_1 R294_2 R294_3 R294_3_1 R295 R295_1 R295_1_1 R295_2 R295_3 R295_3_1 R296 R296_1 R296_1_1 R296_2 R296_3 R296_3_1 R297 R297_1 R297_1_1 R297_2 R297_3 R297_3_1 R298 R298_1 R298_1_1 R298_2 R298_3 R298_3_1 R299 R299_1 R299_1_1 R299_2 R299_3 R299_3_1 R300 R300_1 R300_1_1 R300_2 R300_3 R301 R301_1 R301_1_1 R301_2 R301_3 R301_3_1 R302 R302_1 R302_1_1 R302_2 R302_3 R303 R303_1 R303_1_1 R303_2 R303_3 R304 R304_1 R304_1_1 R304_2 R304_3 R304_3_1 R305 R305_1 R305_1_1 R305_2 R305_3 R305_3_1 R306 R306_1 R306_1_1 R306_2 R306_3 R307 R307_1 R307_1_1 R307_2 R307_3 R308 R308_1 R308_1_1 R308_2 R308_3 R309 R309_1 R309_1_1 R309_2 R309_3 R310 R310_1 R310_1_1 R310_2 R310_3 R311 R311_1 R311_2 R311_2_1 R312 R312_1 R312_2 R312_2_1 R313 R313_1 R313_2 R313_2_1 R314 R314_1 R314_2 R314_2_1 R315 R315_1 R315_2 R315_2_1 R316 R316_1 R316_2 R316_2_1 R317 R317_1 R317_2 R317_2_1 R318 R318_1 R318_2 R318_2_1 R319 R319_1 R319_2 R319_2_1 R320 R320_1 R320_2 R320_2_1 R321 R321_1 R321_2 R321_2_1 R322 R322_1 R322_2 R322_2_1 R323 R323_1 R323_2 R323_2_1 R324 R324_1 R324_2 R324_2_1 R325 R325_1 R325_2 R325_2_1 R326 R326_1 R326_2 R326_2_1 R327 R327_1 R327_2 R327_2_1 R328 R328_1 R328_2 R328_2_1 R329 R329_1 R329_2 R329_2_1 R330 R330_1 R330_2 R330_2_1 R331 R331_1 R331_2 R331_2_1 R332 R332_1 R332_2 R332_2_1 R333 R333_1 R333_2 R333_2_1 R334 R334_1 R334_2 R334_2_1 R335 R335_1 R335_2 R335_2_1 R336 R336_1 R336_2 R336_2_1 R337 R337_1 R337_2 R337_2_1 R338 R338_1 R338_2 R338_2_1 R339 R339_1 R339_2 R339_2_1 R340 R340_1 R340_2 R340_2_1 R341 R341_1 R341_2 R341_2_1 R342 R342_1 R342_2 R342_2_1 R343 R343_1 R343_2 R343_2_1 R344 R344_1 R344_2 R344_2_1 R345 R345_1 R345_2 R345_2_1 R346 R346_1 R346_2 R346_2_1 R347 R347_1 R347_2 R347_2_1 R348 R348_1 R348_2 R348_2_1 R349 R349_1 R349_2 R349_2_1 R350 R350_1 R350_2 R350_2_1 R351 R351_1 R351_2 R351_2_1 R352 R352_1 R352_2 R352_2_1 R353 R353_1 R353_2 R353_2_1 R354 R354_1 R354_2 R354_2_1 R355 R355_1 R355_2 R355_2_1 R356 R356_1 R356_2 R356_2_1 R357 R357_1 R357_2 R357_2_1 R358 R358_1 R358_2 R358_2_1 R359 R359_1 R359_2 R359_2_1 R360 R360_1 R360_2 R360_2_1 R361 R361_1 R361_2 R361_2_1 R362 R362_1 R362_2 R362_2_1 R363 R363_1 R363_2 R363_2_1 R364 R364_1 R364_2 R364_2_1 R365 R365_1 R365_2 R365_2_1 R366 R366_1 R366_2 R366_2_1 R367 R367_1 R367_2 R367_2_1 R368 R368_1 R368_2 R368_2_1 R369 R369_1 R369_2 R369_2_1 R370 R370_1 R370_2 R370_2_1 R371 R371_1 R371_2 R371_2_1 R372 R372_1 R372_2 R372_2_1 R373 R373_1 R373_2 R373_2_1 R374 R374_1 R374_2 R374_2_1 R375 R375_1 R375_2 R375_2_1 R376 R376_1 R376_2 R376_2_1 R377 R377_1 R377_2 R377_2_1 R378 R378_1 R378_2 R378_2_1 R379 R379_1 R379_2 R379_2_1 R380 R380_1 R380_2 R380_2_1 R381 R381_1 R381_2 R381_2_1 R382 R382_1 R382_2 R382_2_1 R383 R383_1 R383_2 R383_2_1 R384 R384_1 R384_2 R384_2_1 R385 R385_1 R385_2 R385_2_1 R386 R386_1 R386_2 R386_2_1 R387 R387_1 R387_2 R387_2_1 R388 R388_1 R388_2 R388_2_1 R389 R389_1 R389_2 R389_2_1 R390 R390_1 R390_2 R390_2_1 R391 R391_1 R391_2 R391_2_1 R392 R392_1 R392_2 R392_2_1 R393 R393_1 R393_2 R393_2_1 R394 R394_1 R394_2 R394_2_1 R395 R395_1 R395_2 R395_2_1 R396 R396_1 R396_2 R396_2_1 R397 R397_1 R397_2 R397_2_1 R398 R398_1 R398_2 R398_2_1 R399 R399_1 R399_2 R399_2_1 R400 R400_1 R400_2 R400_2_1 R401 R401_1 R401_2 R401_2_1 R402 R402_1 R402_2 R402_2_1 R403 R403_1 R403_2 R403_2_1 R404 R404_1 R404_2 R404_2_1 R405 R405_1 R405_2 R405_2_1 R406 R406_1 R406_2 R406_2_1 R407 R407_1 R407_2 R407_2_1 R408 R408_1 R408_2 R408_2_1 R409 R409_1 R409_2 R409_2_1 R410 R410_1 R410_2 R410_2_1 R411 R411_1 R412 R412_1 R413 R413_1 R414 R414_1 R415 R415_1 R416 R416_1 R417 R417_1 R418 R418_1 R418_1_1 R418_2 R419 R419_1 R420 R420_1 R421 R421_1 R422 R422_1 R422_1_1 R422_2 R423 R423_1 R423_1_1 R423_2 R424 R424_1 R425 R425_1 R426 R426_1 R426_1_1 R426_2 R427 R427_1 R427_1_1 R427_2 R428 R428_1 R429 R429_1 R430 R430_1 R431 R431_1 R432 R432_1 R433 R433_1 R434 R434_1 R435 R435_1 R436 R436_1 R437 R437_1 R438 R438_1 R439 R439_1 R440 R440_1 R441 R441_1 R441_1_1 R441_2 R442 R442_1 R443 R443_1 R444 R444_1 R445 R445_1 R446 R446_1 R447 R447_1 R447_1_1 R447_2 R448 R448_1 R449 R449_1 R450 R450_1 R450_1_1 R450_2 R451 R451_1 R452 R452_1 R452_1_1 R452_2 R453 R453_1 R454 R454_1 R455 R455_1 R456 R456_1 R457 R457_1 R458 R458_1 R459 R459_1 R460 R460_1 R461 R461_1 R462 R462_1 R463 R463_1 R463_1_1 R463_2 R464 R464_1 R464_1_1 R464_2 R465 R465_1 R466 R466_1 R467 R467_1 R468 R468_1 R469 R469_1 R470 R470_1 R471 R471_1 R472 R472_1 R473 R473_1 R474 R474_1 R475 R475_1 R475_1_1 R475_2 R476 R476_1 R477 R477_1 R478 R478_1 R479 R479_1 R480 R480_1 R481 R481_1 R482 R482_1 R483 R483_1 R484 R484_1 R484_1_1 R484_2 R485 R485_1 R486 R486_1 R487 R487_1 R488 R488_1 R488_1_1 R488_2 R489 R489_1 R489_1_1 R489_2 R490 R490_1 R491 R491_1 R492 R492_1 R493 R493_1 R494 R494_1 R495 R495_1 R496 R496_1 R497 R497_1 R498 R498_1 R498_1_1 R498_2 R499 R499_1 R500 R500_1 R501 R501_1 R502 R502_1 R502_1_1 R502_2 R503 R503_1 R503_1_1 R503_2 R504 R504_1 R505 R505_1 R506 R506_1 R507 R507_1 R508 R508_1 R508_1_1 R508_2 R509 R509_1 R509_1_1 R509_2 R510 R510_1 R511 R512 R513 R514 R515 R516 R517 R518 R519 R520 R521 R522 R523 R524 R525 R526 R527 R528 R529 R530 R531 R532 R533 R534 R535 R536 R537 R538 R539 R540 R541 R542 R543 R544 R545 R546 R547 R548 R549 R550 R551 R552 R553 R554 R555 R556 R557 R558 R559 R560 R561 R562 R563 R564 R565 R566 R567 R568 R569 R570 R571 R572 R573 R574 R575 R576 R577 R578 R579 R580 R581 R582 R583 R584 R585 R586 R587 R588 R589 R590 R591 R592 R593 R594 R595 R596 R597 R598 R599 R600 R601 R602 R603 R604 R605 R606 R607 R608 R609 R610 R611 R612 R613 R614 R615 R616 R617 R618 R619 R620 R621 R622 R623 R624 R625 R626 R627 R628 R629 R630 R631 R632 R633 R634 R635 R636 R637 R638 R639 R640 R641 R642 R643 R644 R645 R646 R647 R648 R649 R650 R651 R652 R653 R654: library part Resistor
VT1 VT18: library part DPAK, Case=TO-252, Manufacture=TopLine
VT2 VT3 VT4 VT5 VT6 VT7 VT8 VT9 VT10 VT11 VT12 VT13 VT14 VT15 VT16 VT17 VT19: library part SOT-23, Case=SOT23, Manufacture=TopLine
XS1 XS6: library part pld_2_10, Case="PLD 2x10 2.54mm", Manufacture="Chip Dip"
XS2 XS3: Manufacture=Molex
XS4: Case=DIN41612, Manufacture="Chip&Dip xD"
XS5: Manufacture=Chip&Dip
XS7: Manufacture="Chip&Dip xD"

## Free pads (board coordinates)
  rrect50% 1.7x0.2 smd far side: 55(74.5,11.5) 55(74.5,12) 55(74.5,12.5) 55(74.5,13) 55(74.5,13.5) 55(74.5,14) 55(74.5,14.5) 55(74.5,15) 55(74.5,15.5) 55(74.5,16) 55(74.5,16.5) 55(77,11.5) 55(77,12) 55(77,12.5) 55(77,13) 55(77,13.5) 55(77,14) 55(77,14.5) 55(77,15) 55(77,15.5) 55(77,16) 55(77,16.5) 55(79.5,11.5) 55(79.5,12) 55(79.5,12.5) 55(79.5,13) 55(79.5,13.5) 55(79.5,14) 55(79.5,14.5) 55(79.5,15) 55(79.5,15.5) 55(79.5,16) 55(79.5,16.5) 55(82,11.5) 55(82,12) 55(82,12.5) 55(82,13) 55(82,13.5) 55(82,14) 55(82,14.5) 55(82,15) 55(82,15.5) 55(82,16) 55(82,16.5) 55(84.5,11.5) 55(84.5,12) 55(84.5,12.5) 55(84.5,13) 55(84.5,13.5) 55(84.5,14) 55(84.5,14.5) 55(84.5,15) 55(84.5,15.5) 55(84.5,16) 55(84.5,16.5) 55(87,11.5) 55(87,12) 55(87,12.5) 55(87,13) 55(87,13.5) 55(87,14) 55(87,14.5) 55(87,15) 55(87,15.5) 55(87,16) 55(87,16.5)
  rrect50% 1.7x0.35 smd far side: 55(74.5,18.5) 55(74.5,19.25) 55(74.5,20) 55(74.5,20.75) 55(74.5,21.5) 55(74.5,22.25) 55(74.5,23) 55(74.5,23.75) 55(74.5,24.5) 55(74.5,25.25) 55(77,18.5) 55(77,19.25) 55(77,20) 55(77,20.75) 55(77,21.5) 55(77,22.25) 55(77,23) 55(77,23.75) 55(77,24.5) 55(77,25.25) 55(79.5,18.5) 55(79.5,19.25) 55(79.5,20) 55(79.5,20.75) 55(79.5,21.5) 55(79.5,22.25) 55(79.5,23) 55(79.5,23.75) 55(79.5,24.5) 55(79.5,25.25) 55(82,18.5) 55(82,19.25) 55(82,20) 55(82,20.75) 55(82,21.5) 55(82,22.25) 55(82,23) 55(82,23.75) 55(82,24.5) 55(82,25.25) 55(84.5,18.5) 55(84.5,19.25) 55(84.5,20) 55(84.5,20.75) 55(84.5,21.5) 55(84.5,22.25) 55(84.5,23) 55(84.5,23.75) 55(84.5,24.5) 55(84.5,25.25) 55(87,18.5) 55(87,19.25) 55(87,20) 55(87,20.75) 55(87,21.5) 55(87,22.25) 55(87,23) 55(87,23.75) 55(87,24.5) 55(87,25.25)
  rrect50% 1.7x0.5 smd far side: 55(74.5,27.5) 55(74.5,28.5) 55(74.5,29.5) 55(74.5,30.5) 55(74.5,31.5) 55(74.5,32.5) 55(74.5,33.5) 55(77,27.5) 55(77,28.5) 55(77,29.5) 55(77,30.5) 55(77,31.5) 55(77,32.5) 55(77,33.5) 55(79.5,27.5) 55(79.5,28.5) 55(79.5,29.5) 55(79.5,30.5) 55(79.5,31.5) 55(79.5,32.5) 55(79.5,33.5) 55(82,27.5) 55(82,28.5) 55(82,29.5) 55(82,30.5) 55(82,31.5) 55(82,32.5) 55(82,33.5) 55(84.5,27.5) 55(84.5,28.5) 55(84.5,29.5) 55(84.5,30.5) 55(84.5,31.5) 55(84.5,32.5) 55(84.5,33.5) 55(87,27.5) 55(87,28.5) 55(87,29.5) 55(87,30.5) 55(87,31.5) 55(87,32.5) 55(87,33.5)
  round 1.8 hole 1.2: ""(26.6,49.28) ""(26.6,57.75) ""(26.6,66.22) ""(26.6,74.68) ""(34.22,49.28) ""(34.22,57.75) ""(34.22,66.22) ""(34.22,74.68) ""(41.84,49.28) ""(41.84,49.28) ""(41.84,54.36) ""(41.84,59.44) ""(41.84,64.52) ""(41.84,69.6) ""(41.84,74.68) ""(46.92,49.28) ""(46.92,54.36) ""(46.92,59.44) ""(46.92,64.52) ""(46.92,69.6) ""(46.92,74.68) ""(52,49.28) ""(52,54.36) ""(52,59.44) ""(52,64.52) ""(52,69.6) ""(52,74.68) ""(57.08,49.28) ""(57.08,54.36) ""(57.08,59.44) ""(57.08,64.52) ""(57.08,69.6) ""(57.08,74.68) ""(59.64,49.35) ""(59.64,54.43) ""(59.64,59.51) ""(59.64,64.59) ""(59.64,69.67) ""(59.64,74.75) ""(64.72,49.35) ""(64.72,54.43) ""(64.72,59.51) ""(64.72,64.59) ""(64.72,69.67) ""(64.72,74.75) ""(67.26,49.35) ""(67.26,54.43) ""(67.26,59.51) ""(67.26,64.59) ""(67.26,69.67) ""(67.26,74.75) ""(72.34,49.35) ""(72.34,51.89) ""(72.34,54.43) ""(72.34,56.97) ""(72.34,59.51) ""(72.34,62.05) ""(72.34,64.59) ""(72.34,67.13) ""(72.34,69.67) ""(72.34,72.21) ""(72.34,74.75) ""(74.88,49.35) ""(74.88,51.89) ""(74.88,54.43) ""(74.88,56.97) ""(74.88,59.51) ""(74.88,62.05) ""(74.88,64.59) ""(74.88,67.13) ""(74.88,69.67) ""(74.88,72.21) ""(74.88,74.75) ""(77.42,49.35) ""(77.42,51.89) ""(77.42,54.43) ""(77.42,56.97) ""(77.42,59.51) ""(77.42,62.05) ""(77.42,64.59) ""(77.42,67.13) ""(77.42,69.67) ""(77.42,72.21) ""(77.42,74.75) ""(79.96,49.35) ""(79.96,51.89) ""(79.96,54.43) ""(79.96,56.97) ""(79.96,59.51) ""(79.96,62.05) ""(79.96,64.59) ""(79.96,67.13) ""(79.96,69.67) ""(79.96,72.21) ""(79.96,74.75) ""(82.5,49.35) ""(82.5,51.89) ""(82.5,54.43) ""(82.5,56.97) ""(82.5,59.51) ""(82.5,62.05) ""(82.5,64.59) ""(82.5,67.13) ""(82.5,69.67) ""(82.5,72.21) ""(82.5,74.75) ""(85.04,49.35) ""(85.04,51.89) ""(85.04,54.43) ""(85.04,56.97) ""(85.04,59.51) ""(85.04,62.05) ""(85.04,64.59) ""(85.04,67.13) ""(85.04,69.67) ""(85.04,72.21) ""(85.04,74.75) ""(87.58,49.35) ""(87.58,51.89) ""(87.58,54.43) ""(87.58,56.97) ""(87.58,59.51) ""(87.58,62.05) ""(87.58,64.59) ""(87.58,67.13) ""(87.58,69.67) ""(87.58,72.21) ""(87.58,74.75) ""(90.12,49.35) ""(90.12,51.89) ""(90.12,54.43) ""(90.12,56.97) ""(90.12,59.51) ""(90.12,62.05) ""(90.12,64.59) ""(90.12,67.13) ""(90.12,69.67) ""(90.12,72.21) ""(90.12,74.75) ""(92.66,49.35) ""(92.66,51.89) ""(92.66,54.43) ""(92.66,56.97) ""(92.66,59.51) ""(92.66,62.05) ""(92.66,64.59) ""(92.66,67.13) ""(92.66,69.67) ""(92.66,72.21) ""(92.66,74.75) ""(95.2,49.35) ""(95.2,51.89) ""(95.2,54.43) ""(95.2,56.97) ""(95.2,59.51) ""(95.2,62.05) ""(95.2,64.59) ""(95.2,67.13) ""(95.2,69.67) ""(95.2,72.21) ""(95.2,74.75)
